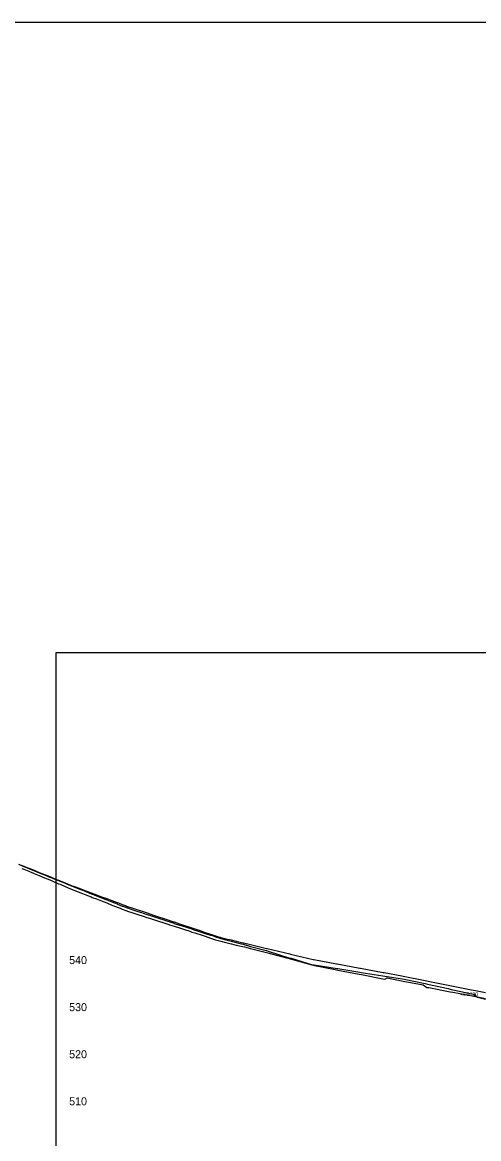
# Model space of a CAD drawing. Extents: x 1979167 to 1986508, y 1111793 to 1113993.
# Drawn here: x 1984194 to 1984680, y 1112807 to 1113993 of the extents above; entities that cross this region are included whole.
import ezdxf

# ---------------------------------------------------------------- set-up
doc = ezdxf.new("R2010")
doc.units = 0
for name, color, linetype in [('BR_EXIST_GROUND_LT', 7, 'Continuous'), ('BR_EXIST_GROUND_RT', 7, 'Continuous'), ('BR_USER NOTES', 7, 'Continuous'), ('RD_DDB_ElevTX', 7, 'Continuous'), ('RD_DDB_Profile_EX', 7, 'Continuous'), ('RD_SHT_IplotShp', 7, 'Continuous'), ('RD_SHT_ShtClip', 7, 'Continuous')]:
    doc.layers.add(name, color=color, linetype=linetype)

msp = doc.modelspace()

# ---------------------------------------------------------------- linework, layer by layer
at = {"layer": 'BR_EXIST_GROUND_LT'}
msp.add_lwpolyline([(1984193.9, 1113094), (1984195.9, 1113093.2), (1984201.4, 1113090.9), (1984204.5, 1113089.6), (1984205.4, 1113089.2), (1984206.9, 1113088.6), (1984212.4, 1113086.3), (1984217.9, 1113084), (1984223.5, 1113081.7), (1984227.4, 1113080), (1984229, 1113079.3), (1984230.5, 1113078.7), (1984232.9, 1113077.7), (1984234.5, 1113077.1), (1984240, 1113074.7), (1984245.5, 1113072.4), (1984248.3, 1113071.2), (1984251, 1113070.1), (1984256.5, 1113068), (1984262, 1113065.8), (1984267.6, 1113063.6), (1984268.7, 1113063.2), (1984273.3, 1113061.5), (1984278.6, 1113059.4), (1984284.1, 1113057.2), (1984289.6, 1113055), (1984294.5, 1113053.1), (1984295.1, 1113052.8), (1984298.4, 1113051.6), (1984300.6, 1113050.7), (1984304.5, 1113049.2), (1984305.6, 1113048.7), (1984306.1, 1113048.6), (1984311.7, 1113046.8), (1984317.2, 1113045), (1984322.7, 1113043.2), (1984326.8, 1113041.8), (1984328.2, 1113041.4), (1984330.8, 1113040.7), (1984333.7, 1113039.7), (1984339.2, 1113037.9), (1984344.7, 1113036), (1984350.2, 1113034.2), (1984350.9, 1113034), (1984355.9, 1113032.5), (1984361.3, 1113030.8), (1984366.8, 1113028.9), (1984372.3, 1113027.1), (1984374.6, 1113026.3), (1984377.8, 1113025.4), (1984381, 1113024.4), (1984383.3, 1113023.7), (1984388.8, 1113021.8), (1984394.3, 1113020), (1984397.7, 1113018.9), (1984399.9, 1113018.2), (1984405.5, 1113016.6), (1984410.9, 1113015.2), (1984416.4, 1113013.8), (1984416.8, 1113013.7), (1984421.9, 1113012.5), (1984430.6, 1113010.5), (1984437, 1113008.8), (1984445.5, 1113006.6), (1984455.5, 1113004.2), (1984475.1, 1112998.9), (1984480.5, 1112997.6), (1984502.2, 1112991.6), (1984504.7, 1112991.4), (1984529, 1112987.6), (1984529.8, 1112987.5), (1984553.4, 1112983.8), (1984554.8, 1112983.5), (1984577.9, 1112979.9), (1984579.9, 1112979.5), (1984598.6, 1112976.6), (1984600.4, 1112976.2), (1984622.6, 1112971.7), (1984625.4, 1112970.8), (1984647.3, 1112966.3), (1984650.4, 1112965.4), (1984652.3, 1112964.8), (1984674.2, 1112960.2), (1984678.5, 1112957), (1984687, 1112955.2)], dxfattribs=at)
at = {"layer": 'BR_EXIST_GROUND_RT'}
msp.add_lwpolyline([(1984190.4, 1113098.3), (1984195.9, 1113096.1), (1984200.4, 1113094.2), (1984201.4, 1113093.8), (1984207.1, 1113091.5), (1984212.4, 1113089.3), (1984217.9, 1113087.1), (1984223.5, 1113084.8), (1984224, 1113084.6), (1984229, 1113082.6), (1984231.9, 1113081.3), (1984234.5, 1113080.3), (1984240, 1113078.1), (1984241.2, 1113077.6), (1984245.5, 1113075.8), (1984245.9, 1113075.7), (1984251, 1113073.7), (1984256.1, 1113071.6), (1984256.5, 1113071.5), (1984262, 1113069.3), (1984267.6, 1113067.1), (1984270.7, 1113065.8), (1984273.1, 1113064.9), (1984278.6, 1113062.7), (1984283.3, 1113060.9), (1984284.1, 1113060.6), (1984289.6, 1113058.4), (1984295.1, 1113056.2), (1984295.5, 1113056.1), (1984300.6, 1113054), (1984301.3, 1113053.8), (1984305.8, 1113052), (1984306.1, 1113051.9), (1984311.7, 1113050.1), (1984317.2, 1113048.3), (1984321, 1113047.1), (1984322.7, 1113046.5), (1984328.2, 1113044.6), (1984330.6, 1113043.8), (1984333.7, 1113042.8), (1984339.2, 1113041), (1984344.7, 1113039.3), (1984346.7, 1113038.7), (1984350.2, 1113037.4), (1984355.4, 1113035.7), (1984355.8, 1113035.5), (1984361.3, 1113033.8), (1984366.8, 1113032.1), (1984372, 1113030.4), (1984372.3, 1113030.3), (1984377.8, 1113028.4), (1984380.2, 1113027.6), (1984383.3, 1113026.6), (1984388.8, 1113024.9), (1984394.3, 1113023.1), (1984396.5, 1113022.5), (1984399.9, 1113021.3), (1984404.5, 1113019.7), (1984405.4, 1113019.5), (1984410.9, 1113018), (1984416.4, 1113016.6), (1984421.9, 1113015.1), (1984424.1, 1113014.5), (1984429.2, 1113013.3), (1984437, 1113011.1), (1984453.6, 1113006.7), (1984454, 1113006.6), (1984455.9, 1113006.1), (1984478.9, 1112998.7), (1984480.3, 1112998.5), (1984503.9, 1112991.2), (1984505.1, 1112990.9), (1984527.2, 1112986.5), (1984530, 1112986), (1984552.5, 1112981.6), (1984554.9, 1112981.2), (1984577.7, 1112976.7), (1984579.8, 1112976.3), (1984582.5, 1112977.6), (1984599.4, 1112974.3), (1984620.7, 1112970.3), (1984624.5, 1112967.6), (1984626.8, 1112967.3), (1984649.5, 1112962.9), (1984652.3, 1112962.5), (1984674.4, 1112958.2), (1984676.6, 1112957.9), (1984687, 1112955.9)], dxfattribs=at)
at = {"layer": 'RD_DDB_Profile_EX'}
msp.add_lwpolyline([(1984190.4, 1113098.6), (1984195.9, 1113096.4), (1984201.4, 1113094.2), (1984202.2, 1113093.8), (1984206.9, 1113092), (1984207.6, 1113091.7), (1984212.4, 1113089.7), (1984217.9, 1113087.5), (1984223.5, 1113085.2), (1984229, 1113083), (1984231.6, 1113081.9), (1984232.1, 1113081.7), (1984234.5, 1113080.8), (1984240, 1113078.5), (1984245.5, 1113076.3), (1984246.6, 1113075.8), (1984247.3, 1113075.6), (1984251, 1113074.2), (1984256.5, 1113072.1), (1984262, 1113070.1), (1984267.6, 1113068), (1984271.6, 1113066.5), (1984272.1, 1113066.3), (1984273.1, 1113065.9), (1984278.6, 1113063.9), (1984284.1, 1113061.8), (1984289.6, 1113059.8), (1984295.1, 1113057.7), (1984296.6, 1113057.2), (1984300.6, 1113055.6), (1984303.9, 1113054.4), (1984305.2, 1113053.9), (1984306.2, 1113053.6), (1984311.7, 1113051.8), (1984317.2, 1113050), (1984322.7, 1113048.1), (1984328.2, 1113046.3), (1984329.5, 1113045.8), (1984330.1, 1113045.6), (1984333.7, 1113044.4), (1984339.2, 1113042.6), (1984344.7, 1113040.8), (1984350.2, 1113038.9), (1984354.1, 1113037.6), (1984355.1, 1113037.3), (1984355.8, 1113037.1), (1984361.3, 1113035.2), (1984366.8, 1113033.4), (1984372.3, 1113031.6), (1984377.8, 1113029.7), (1984379, 1113029.3), (1984380, 1113029), (1984383.3, 1113027.9), (1984388.8, 1113026), (1984394.3, 1113024.2), (1984399.9, 1113022.4), (1984403.9, 1113021), (1984404.7, 1113020.8), (1984405.4, 1113020.6), (1984410.9, 1113019.3), (1984416.4, 1113018), (1984421.9, 1113016.7), (1984428.8, 1113015), (1984429.6, 1113014.8), (1984437, 1113013), (1984453.9, 1113009), (1984454.6, 1113008.9), (1984478.9, 1113003.1), (1984479.6, 1113002.9), (1984503.6, 1112997.2), (1984504.2, 1112997.1), (1984528.4, 1112992.6), (1984529.2, 1112992.5), (1984553.2, 1112988.1), (1984554.1, 1112987.9), (1984578, 1112983.5), (1984579.1, 1112983.3), (1984598.1, 1112979.8), (1984599.2, 1112979.6), (1984622.6, 1112974.9), (1984624.2, 1112974.6), (1984647.3, 1112970), (1984649.1, 1112969.6), (1984672, 1112965), (1984674.1, 1112964.6), (1984676.2, 1112964.2), (1984687, 1112962)], dxfattribs=at)
at = {"layer": 'RD_SHT_IplotShp'}
msp.add_lwpolyline([(1986508.5, 1113992.7), (1982908.5, 1113992.7), (1982908.5, 1111792.7), (1986508.5, 1111792.7)], close=True, dxfattribs=at)
at = {"layer": 'RD_SHT_ShtClip'}
msp.add_lwpolyline([(1984230.3, 1113323.3), (1986030.3, 1113323.3), (1986030.3, 1112223.3), (1984230.3, 1112223.3)], close=True, dxfattribs=at)

# ---------------------------------------------------------------- texts
at = {"layer": 'BR_USER NOTES'}
msp.add_text('-4.0020', height=4, dxfattribs=at).set_placement((1984660.3, 1112958.3))
at = {"layer": 'RD_DDB_ElevTX'}
for s, p in [('540', (1984244.1, 1112992.3)), ('530', (1984244.1, 1112942.3)), ('520', (1984244.1, 1112892.3)), ('510', (1984244.1, 1112842.3))]:
    msp.add_text(s, height=8.5, dxfattribs=at).set_placement(p)

doc.saveas('drawing.dxf')
